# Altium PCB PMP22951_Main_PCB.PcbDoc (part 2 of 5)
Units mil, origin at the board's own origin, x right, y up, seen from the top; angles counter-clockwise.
Board outline 6643.5 x 4153.54 mil, 6 copper layers (Top Layer, Signal Layer 1, Signal Layer 2, Signal Layer 3, Signal Layer 4, Bottom Layer), stack 65.8 mil thick; 139 components, 80 nets, 687 pads, 417 vias.
Unrouted connection lines stored in the file: 2.
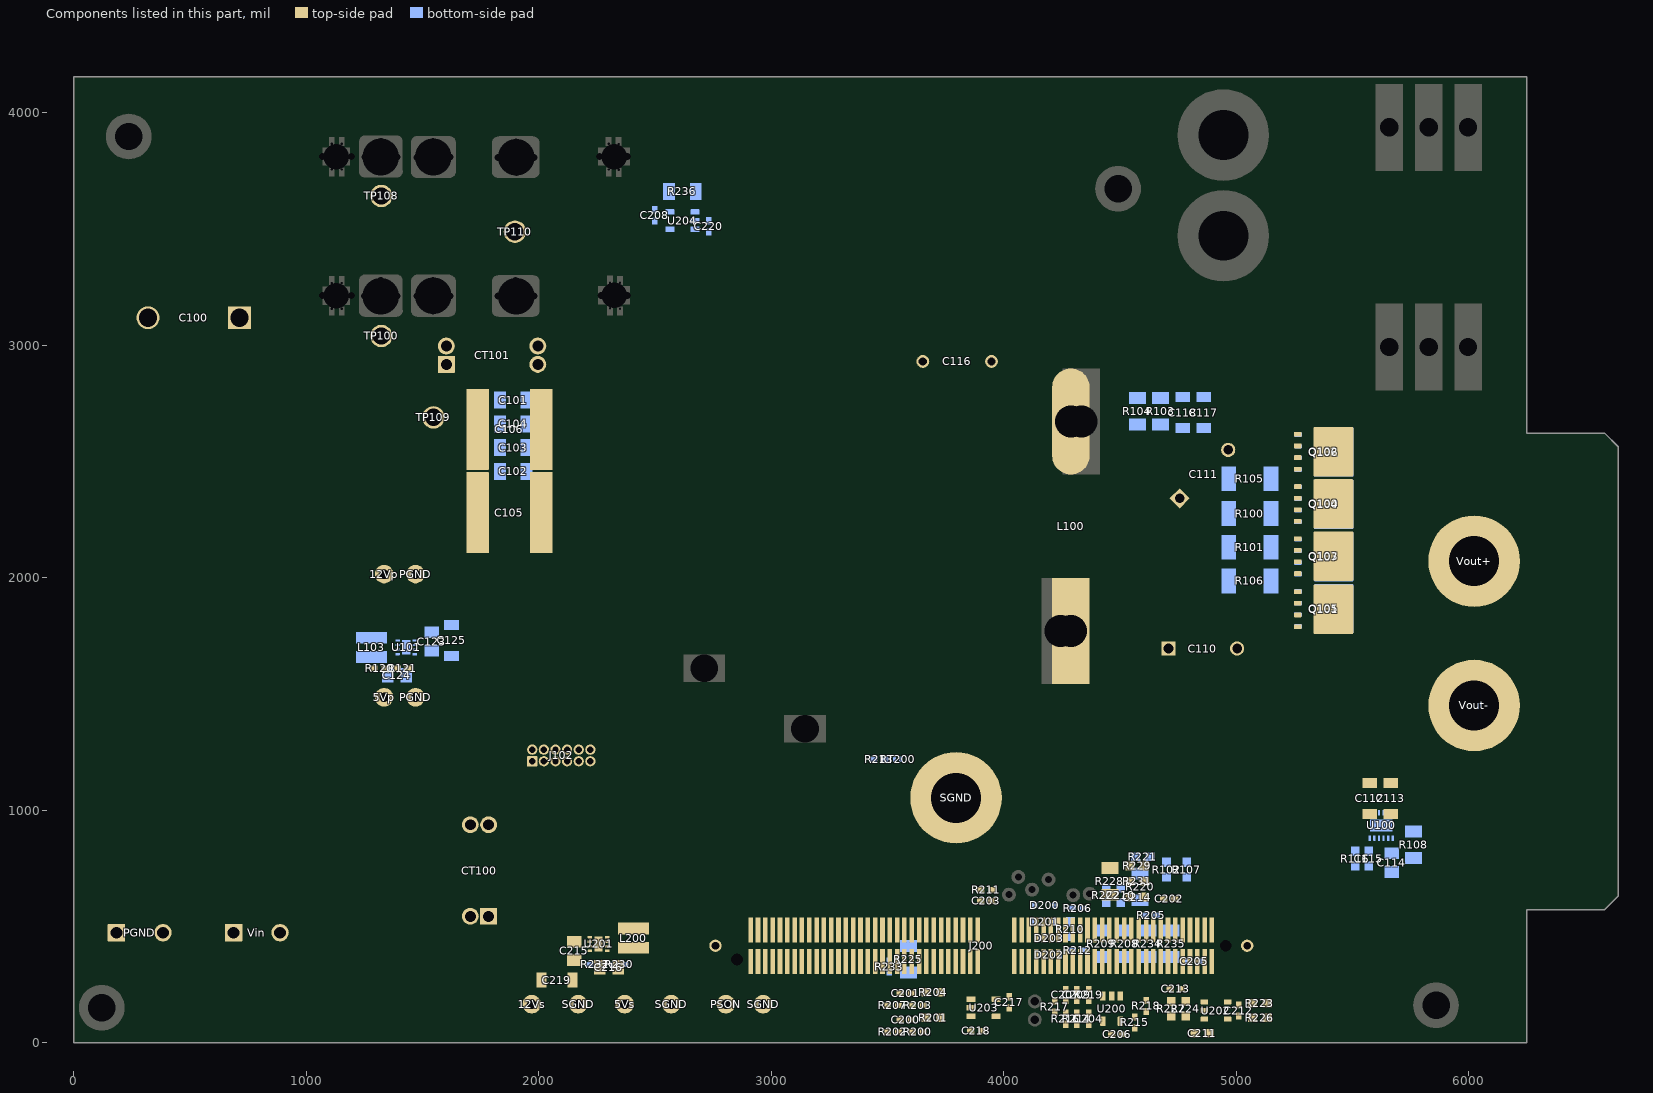
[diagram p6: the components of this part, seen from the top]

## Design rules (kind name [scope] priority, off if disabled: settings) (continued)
PolygonConnect PolygonConnect_49 [All vs IsNamedPolygon('BOTTOM_LAYER_54V1_P128')] p20: connectstyle=Direct reliefconductorwidth=10 reliefentries=4 polygonreliefangle="90 Angle" airgapwidth=10
PolygonConnect PolygonConnect_48 [All vs IsNamedPolygon('BOTTOM_LAYER_54V1_P128')] p21: connectstyle=Direct reliefconductorwidth=10 reliefentries=4 polygonreliefangle="90 Angle" airgapwidth=10
PolygonConnect PolygonConnect_47 [All vs IsNamedPolygon('BOTTOM_LAYER_54V1_P128')] p22: connectstyle=Direct reliefconductorwidth=10 reliefentries=4 polygonreliefangle="90 Angle" airgapwidth=10
PolygonConnect PolygonConnect_46 [All vs IsNamedPolygon('PGND') Or  IsNamedPolygon('T200_4') Or  IsNamedPolygon('VBB') Or  IsNamedPolygon('SWNODE3') Or  IsNamedPolygon('LEG4_LS_DRV') Or  IsNamedPolygon('Iout_SNS') Or  IsNamedPolygon('SWNODE3') Or  IsNamedPolygon('T200_6') Or  IsNamedPolygon('SGND') Or  IsNamedPolygon('SIGNAL_LAYER_1_VBULK1_P106') Or  IsNamedPolygon('LEG3_HS_DRV') Or  IsNamedPolygon('TOP_LAYER_12VS_P126') Or  IsNamedPolygon('LEG4_HS_DRV') Or  IsNamedPolygon('SWNODE3') Or  IsNamedPolygon('SGND') Or  IsNamedPolygon('BOTTOM_LAYER_54V1_P128') Or  IsNamedPolygon('SGND') Or  IsNamedPolygon('Line') Or  IsNamedPolygon('TOP_LAYER_IOUT_SNS_P092') Or  IsNamedPolygon('C108_1') Or  IsNamedPolygon('D403_2') Or  IsNamedPolygon('SWNODE') Or  IsNamedPolygon('SIGNAL_LAYER_2_VBB_P094') Or  IsNamedPolygon('Vbulk') Or  IsNamedPolygon('D404_2') Or  IsNamedPolygon('VSR') Or  IsNamedPolygon('C108_1') Or  IsNamedPolygon('C108_1') Or  IsNamedPolygon('5Vp') Or  IsNamedPolygon('C108_1') Or  IsNamedPolygon('PGND') Or  IsNamedPolygon('D400_2') Or  IsNamedPolygon('SWNODE3') Or  IsNamedPolygon('Line') Or  IsNamedPolygon('C108_1') Or  IsNamedPolygon('TOP_LAYER_VBULK_P104') Or  IsNamedPolygon('Vbulk1') Or  IsNamedPolygon('T200_6') Or  IsNamedPolygon('T200_6') Or  IsNamedPolygon('SWNODE4') Or  IsNamedPolygon('C108_1') Or  IsNamedPolygon('D403_2') Or  IsNamedPolygon('PGND') Or  IsNamedPolygon('T200_4') Or  IsNamedPolygon('Line') Or  IsNamedPolygon('5Vs') Or  IsNamedPolygon('12Vp') Or  IsNamedPolygon('C102_1') Or  IsNamedPolygon('SGND') Or  IsNamedPolygon('TOP_LAYER_54V2_P048') Or  IsNamedPolygon('TOP_LAYER_54V1_P046') Or  IsNamedPolygon('SWNODE4') Or  IsNamedPolygon('ZCD') Or  IsNamedPolygon('SWNODE3') Or  IsNamedPolygon('SWNODE3') Or  IsNamedPolygon('BOTTOM_LAYER_NETC106_2_P030') Or  IsNamedPolygon('TOP_LAYER_54V2_P048') Or  IsNamedPolygon('T200_4') Or  IsNamedPolygon('SWNODE4') Or  IsNamedPolygon('SWNODE4') Or  IsNamedPolygon('SGND') Or  IsNamedPolygon('SGND') Or  IsNamedPolygon('SGND') Or  IsNamedPolygon('SWNODE4') Or  IsNamedPolygon('VSR') Or  IsNamedPolygon('SWNODE3') Or  IsNamedPolygon('SGND') Or  IsNamedPolygon('SGND') Or  IsNamedPolygon('SGND') Or  IsNamedPolygon('SGND') Or  IsNamedPolygon('SGND') Or  IsNamedPolygon('SGND') Or  IsNamedPolygon('BOTTOM_LAYER_54V1_P128') Or  IsNamedPolygon('SGND') Or  IsNamedPolygon('VSR') Or  IsNamedPolygon('C102_1') Or  IsNamedPolygon('C102_1') Or  IsNamedPolygon('C102_1') Or  IsNamedPolygon('C102_1') Or  IsNamedPolygon('C102_1') Or  IsNamedPolygon('ZCD') Or  IsNamedPolygon('PGND') Or  IsNamedPolygon('PGND') Or  IsNamedPolygon('Vbulk1') Or  IsNamedPolygon('Vbulk') Or  IsNamedPolygon('Vbulk1') Or  IsNamedPolygon('Vbulk1') Or  IsNamedPolygon('ZCD') Or  IsNamedPolygon('Neutral') Or  IsNamedPolygon('Neutral') Or  IsNamedPolygon('C106_2') Or  IsNamedPolygon('C106_2') Or  IsNamedPolygon('C106_2') Or  IsNamedPolygon('SWNODE') Or  IsNamedPolygon('Vbulk1') Or  IsNamedPolygon('Earth1') Or  IsNamedPolygon('Earth1') Or  IsNamedPolygon('Earth1') Or  IsNamedPolygon('Earth1') Or  IsNamedPolygon('Earth1') Or  IsNamedPolygon('Earth1') Or  IsNamedPolygon('ZCD') Or  IsNamedPolygon('VBB') Or  IsNamedPolygon('PGND') Or  IsNamedPolygon('D106_1') Or  IsNamedPolygon('PGND') Or  IsNamedPolygon('PGND') Or  IsNamedPolygon('D106_1') Or  IsNamedPolygon('Vbulk') Or  IsNamedPolygon('D106_1') Or  IsNamedPolygon('PGND') Or  IsNamedPolygon('VBB') Or  IsNamedPolygon('VBB') Or  IsNamedPolygon('PGND') Or  IsNamedPolygon('PGND') Or  IsNamedPolygon('PGND') Or  IsNamedPolygon('PGND') Or  IsNamedPolygon('PGND') Or  IsNamedPolygon('ZCD') Or  IsNamedPolygon('ZCD') Or  IsNamedPolygon('C412_2') Or  IsNamedPolygon('VBB') Or  IsNamedPolygon('PGND') Or  IsNamedPolygon('PGND') Or  IsNamedPolygon('PGND') Or  IsNamedPolygon('PGND') Or  IsNamedPolygon('PGND') Or  IsNamedPolygon('PGND') Or  IsNamedPolygon('PGND') Or  IsNamedPolygon('Vbulk') Or  IsNamedPolygon('D404_2') Or  IsNamedPolygon('PGND') Or  IsNamedPolygon('Iout_SNS') Or  IsNamedPolygon('54V2')] p23: connectstyle=Direct reliefconductorwidth=10 reliefentries=4 polygonreliefangle="90 Angle" airgapwidth=10
PolygonConnect PolygonConnect_45 [All vs IsNamedPolygon('Vbulk1') Or  IsNamedPolygon('TOP_LAYER_VBULK_P104') Or  IsNamedPolygon('SIGNAL_LAYER_1_VBULK1_P106') Or  IsNamedPolygon('Iout_SNS') Or  IsNamedPolygon('SIGNAL_LAYER_2_VBB_P094') Or  IsNamedPolygon('Line') Or  IsNamedPolygon('T200_4') Or  IsNamedPolygon('ZCD') Or  IsNamedPolygon('C108_1') Or  IsNamedPolygon('PGND') Or  IsNamedPolygon('BOTTOM_LAYER_NETC106_2_P030') Or  IsNamedPolygon('5Vp') Or  IsNamedPolygon('C108_1') Or  IsNamedPolygon('Line') Or  IsNamedPolygon('C102_1') Or  IsNamedPolygon('T200_4') Or  IsNamedPolygon('12Vp') Or  IsNamedPolygon('D403_2') Or  IsNamedPolygon('T200_6') Or  IsNamedPolygon('TOP_LAYER_54V1_P046') Or  IsNamedPolygon('TOP_LAYER_54V2_P048') Or  IsNamedPolygon('C108_1') Or  IsNamedPolygon('C108_1') Or  IsNamedPolygon('SWNODE3') Or  IsNamedPolygon('TOP_LAYER_54V2_P048') Or  IsNamedPolygon('PGND') Or  IsNamedPolygon('D403_2') Or  IsNamedPolygon('C108_1') Or  IsNamedPolygon('C108_1') Or  IsNamedPolygon('T200_6') Or  IsNamedPolygon('SGND') Or  IsNamedPolygon('SWNODE') Or  IsNamedPolygon('SGND') Or  IsNamedPolygon('SWNODE3') Or  IsNamedPolygon('BOTTOM_LAYER_54V1_P128') Or  IsNamedPolygon('C102_1') Or  IsNamedPolygon('SWNODE4') Or  IsNamedPolygon('C102_1') Or  IsNamedPolygon('SGND') Or  IsNamedPolygon('C102_1') Or  IsNamedPolygon('SGND') Or  IsNamedPolygon('VSR') Or  IsNamedPolygon('SGND') Or  IsNamedPolygon('SGND') Or  IsNamedPolygon('VSR') Or  IsNamedPolygon('SGND') Or  IsNamedPolygon('SWNODE4') Or  IsNamedPolygon('SGND') Or  IsNamedPolygon('SGND') Or  IsNamedPolygon('Vbulk1') Or  IsNamedPolygon('SGND') Or  IsNamedPolygon('PGND') Or  IsNamedPolygon('SGND') Or  IsNamedPolygon('PGND') Or  IsNamedPolygon('SWNODE3') Or  IsNamedPolygon('ZCD') Or  IsNamedPolygon('VSR') Or  IsNamedPolygon('C102_1') Or  IsNamedPolygon('SWNODE4') Or  IsNamedPolygon('C102_1') Or  IsNamedPolygon('SWNODE4') Or  IsNamedPolygon('SWNODE3') Or  IsNamedPolygon('PGND') Or  IsNamedPolygon('SGND') Or  IsNamedPolygon('D400_2') Or  IsNamedPolygon('SGND') Or  IsNamedPolygon('5Vs') Or  IsNamedPolygon('VBB') Or  IsNamedPolygon('T200_4') Or  IsNamedPolygon('T200_6') Or  IsNamedPolygon('SWNODE4') Or  IsNamedPolygon('LEG4_HS_DRV') Or  IsNamedPolygon('LEG4_LS_DRV') Or  IsNamedPolygon('LEG3_HS_DRV') Or  IsNamedPolygon('BOTTOM_LAYER_54V1_P128') Or  IsNamedPolygon('TOP_LAYER_12VS_P126') Or  IsNamedPolygon('Iout_SNS') Or  IsNamedPolygon('SWNODE3') Or  IsNamedPolygon('SWNODE3') Or  IsNamedPolygon('SWNODE3') Or  IsNamedPolygon('VBB') Or  IsNamedPolygon('Line') Or  IsNamedPolygon('D404_2') Or  IsNamedPolygon('SGND') Or  IsNamedPolygon('VBB') Or  IsNamedPolygon('VBB') Or  IsNamedPolygon('PGND') Or  IsNamedPolygon('PGND') Or  IsNamedPolygon('PGND') Or  IsNamedPolygon('PGND') Or  IsNamedPolygon('PGND') Or  IsNamedPolygon('ZCD') Or  IsNamedPolygon('ZCD') Or  IsNamedPolygon('C412_2') Or  IsNamedPolygon('VBB') Or  IsNamedPolygon('PGND') Or  IsNamedPolygon('PGND') Or  IsNamedPolygon('PGND') Or  IsNamedPolygon('PGND') Or  IsNamedPolygon('PGND') Or  IsNamedPolygon('PGND') Or  IsNamedPolygon('PGND') Or  IsNamedPolygon('VBB') Or  IsNamedPolygon('D404_2') Or  IsNamedPolygon('VBB') Or  IsNamedPolygon('Vbulk1') Or  IsNamedPolygon('Vbulk1') Or  IsNamedPolygon('ZCD') Or  IsNamedPolygon('Neutral') Or  IsNamedPolygon('Neutral') Or  IsNamedPolygon('C106_2') Or  IsNamedPolygon('C106_2') Or  IsNamedPolygon('C106_2') Or  IsNamedPolygon('SWNODE') Or  IsNamedPolygon('Vbulk1') Or  IsNamedPolygon('Earth1') Or  IsNamedPolygon('Earth1') Or  IsNamedPolygon('Earth1') Or  IsNamedPolygon('Earth1') Or  IsNamedPolygon('Earth1') Or  IsNamedPolygon('Earth1') Or  IsNamedPolygon('ZCD') Or  IsNamedPolygon('VBB') Or  IsNamedPolygon('PGND') Or  IsNamedPolygon('D106_1') Or  IsNamedPolygon('PGND') Or  IsNamedPolygon('PGND') Or  IsNamedPolygon('D106_1') Or  IsNamedPolygon('VBB') Or  IsNamedPolygon('D106_1') Or  IsNamedPolygon('PGND')] p24: connectstyle=Direct reliefconductorwidth=10 reliefentries=4 polygonreliefangle="90 Angle" airgapwidth=10
PolygonConnect PolygonConnect_44 [All vs IsNamedPolygon('Earth1') Or  IsNamedPolygon('Vbulk1') Or  IsNamedPolygon('Vbulk1') Or  IsNamedPolygon('VBB') Or  IsNamedPolygon('Vbulk1') Or  IsNamedPolygon('ZCD') Or  IsNamedPolygon('VBB') Or  IsNamedPolygon('PGND') Or  IsNamedPolygon('C412_2') Or  IsNamedPolygon('ZCD') Or  IsNamedPolygon('D106_1') Or  IsNamedPolygon('D106_1') Or  IsNamedPolygon('ZCD') Or  IsNamedPolygon('PGND') Or  IsNamedPolygon('PGND') Or  IsNamedPolygon('ZCD') Or  IsNamedPolygon('VBB') Or  IsNamedPolygon('PGND') Or  IsNamedPolygon('VBB') Or  IsNamedPolygon('PGND') Or  IsNamedPolygon('D106_1') Or  IsNamedPolygon('PGND') Or  IsNamedPolygon('PGND') Or  IsNamedPolygon('PGND') Or  IsNamedPolygon('VBB') Or  IsNamedPolygon('PGND') Or  IsNamedPolygon('PGND') Or  IsNamedPolygon('C102_1') Or  IsNamedPolygon('ZCD') Or  IsNamedPolygon('C102_1') Or  IsNamedPolygon('C102_1') Or  IsNamedPolygon('C102_1') Or  IsNamedPolygon('PGND') Or  IsNamedPolygon('C102_1') Or  IsNamedPolygon('Line') Or  IsNamedPolygon('T200_4') Or  IsNamedPolygon('T200_4') Or  IsNamedPolygon('SIGNAL_LAYER_1_VBULK1_P106') Or  IsNamedPolygon('TOP_LAYER_VBULK_P104') Or  IsNamedPolygon('T200_4') Or  IsNamedPolygon('SGND') Or  IsNamedPolygon('T200_6') Or  IsNamedPolygon('C108_1') Or  IsNamedPolygon('SWNODE3') Or  IsNamedPolygon('SWNODE') Or  IsNamedPolygon('SWNODE3') Or  IsNamedPolygon('LEG3_HS_DRV') Or  IsNamedPolygon('BOTTOM_LAYER_NETC106_2_P030') Or  IsNamedPolygon('C102_1') Or  IsNamedPolygon('SWNODE4') Or  IsNamedPolygon('SIGNAL_LAYER_2_VBB_P094') Or  IsNamedPolygon('SGND') Or  IsNamedPolygon('VSR') Or  IsNamedPolygon('C108_1') Or  IsNamedPolygon('BOTTOM_LAYER_54V1_P128') Or  IsNamedPolygon('TOP_LAYER_54V2_P048') Or  IsNamedPolygon('TOP_LAYER_54V1_P046') Or  IsNamedPolygon('C108_1') Or  IsNamedPolygon('D403_2') Or  IsNamedPolygon('ZCD') Or  IsNamedPolygon('PGND') Or  IsNamedPolygon('SWNODE3') Or  IsNamedPolygon('Line') Or  IsNamedPolygon('D400_2') Or  IsNamedPolygon('SGND') Or  IsNamedPolygon('PGND') Or  IsNamedPolygon('SGND') Or  IsNamedPolygon('LEG4_HS_DRV') Or  IsNamedPolygon('SWNODE3') Or  IsNamedPolygon('5Vs') Or  IsNamedPolygon('SWNODE4') Or  IsNamedPolygon('SGND') Or  IsNamedPolygon('SGND') Or  IsNamedPolygon('C108_1') Or  IsNamedPolygon('5Vp') Or  IsNamedPolygon('12Vp') Or  IsNamedPolygon('Iout_SNS') Or  IsNamedPolygon('D404_2') Or  IsNamedPolygon('SGND') Or  IsNamedPolygon('T200_6') Or  IsNamedPolygon('TOP_LAYER_54V2_P048') Or  IsNamedPolygon('SGND') Or  IsNamedPolygon('SWNODE3') Or  IsNamedPolygon('SWNODE4') Or  IsNamedPolygon('Iout_SNS') Or  IsNamedPolygon('C108_1') Or  IsNamedPolygon('BOTTOM_LAYER_54V1_P128') Or  IsNamedPolygon('SWNODE3') Or  IsNamedPolygon('LEG4_LS_DRV') Or  IsNamedPolygon('SGND') Or  IsNamedPolygon('SWNODE4') Or  IsNamedPolygon('T200_6') Or  IsNamedPolygon('TOP_LAYER_12VS_P126') Or  IsNamedPolygon('Line') Or  IsNamedPolygon('Vbulk1') Or  IsNamedPolygon('SWNODE3') Or  IsNamedPolygon('SGND') Or  IsNamedPolygon('VBB') Or  IsNamedPolygon('SGND') Or  IsNamedPolygon('SGND') Or  IsNamedPolygon('SWNODE4') Or  IsNamedPolygon('PGND') Or  IsNamedPolygon('D403_2') Or  IsNamedPolygon('VSR') Or  IsNamedPolygon('SGND') Or  IsNamedPolygon('SGND') Or  IsNamedPolygon('VBB') Or  IsNamedPolygon('C108_1') Or  IsNamedPolygon('Earth1') Or  IsNamedPolygon('Earth1') Or  IsNamedPolygon('VSR') Or  IsNamedPolygon('C106_2') Or  IsNamedPolygon('Vbulk1') Or  IsNamedPolygon('C106_2') Or  IsNamedPolygon('C106_2') Or  IsNamedPolygon('Earth1') Or  IsNamedPolygon('SWNODE') Or  IsNamedPolygon('Neutral') Or  IsNamedPolygon('Earth1') Or  IsNamedPolygon('Earth1') Or  IsNamedPolygon('Neutral')] p25: connectstyle=Direct reliefconductorwidth=10 reliefentries=4 polygonreliefangle="90 Angle" airgapwidth=10
PolygonConnect PolygonConnect_43 [All vs IsNamedPolygon('SWNODE') Or  IsNamedPolygon('D403_2') Or  IsNamedPolygon('D403_2') Or  IsNamedPolygon('PGND') Or  IsNamedPolygon('BOTTOM_LAYER_NETC106_2_P030') Or  IsNamedPolygon('C102_1') Or  IsNamedPolygon('SGND') Or  IsNamedPolygon('TOP_LAYER_54V1_P046') Or  IsNamedPolygon('TOP_LAYER_54V2_P048') Or  IsNamedPolygon('TOP_LAYER_54V2_P048') Or  IsNamedPolygon('C108_1') Or  IsNamedPolygon('C108_1') Or  IsNamedPolygon('C108_1') Or  IsNamedPolygon('C108_1') Or  IsNamedPolygon('C108_1') Or  IsNamedPolygon('C108_1') Or  IsNamedPolygon('PGND') Or  IsNamedPolygon('ZCD') Or  IsNamedPolygon('Line') Or  IsNamedPolygon('5Vp') Or  IsNamedPolygon('12Vp') Or  IsNamedPolygon('T200_4') Or  IsNamedPolygon('T200_6') Or  IsNamedPolygon('SWNODE3') Or  IsNamedPolygon('T200_4') Or  IsNamedPolygon('T200_6') Or  IsNamedPolygon('SWNODE4') Or  IsNamedPolygon('VSR') Or  IsNamedPolygon('Iout_SNS') Or  IsNamedPolygon('SIGNAL_LAYER_2_VBB_P094') Or  IsNamedPolygon('Vbulk1') Or  IsNamedPolygon('TOP_LAYER_VBULK_P104') Or  IsNamedPolygon('SIGNAL_LAYER_1_VBULK1_P106') Or  IsNamedPolygon('Line') Or  IsNamedPolygon('Line') Or  IsNamedPolygon('D404_2') Or  IsNamedPolygon('VBB') Or  IsNamedPolygon('D400_2') Or  IsNamedPolygon('SGND') Or  IsNamedPolygon('PGND') Or  IsNamedPolygon('TOP_LAYER_12VS_P126') Or  IsNamedPolygon('BOTTOM_LAYER_54V1_P128') Or  IsNamedPolygon('LEG3_HS_DRV') Or  IsNamedPolygon('LEG4_LS_DRV') Or  IsNamedPolygon('LEG4_HS_DRV') Or  IsNamedPolygon('SWNODE4') Or  IsNamedPolygon('SWNODE3') Or  IsNamedPolygon('T200_6') Or  IsNamedPolygon('T200_4') Or  IsNamedPolygon('VBB') Or  IsNamedPolygon('5Vs') Or  IsNamedPolygon('SGND') Or  IsNamedPolygon('Iout_SNS') Or  IsNamedPolygon('SGND') Or  IsNamedPolygon('SWNODE3') Or  IsNamedPolygon('SWNODE3') Or  IsNamedPolygon('SWNODE3') Or  IsNamedPolygon('SWNODE3') Or  IsNamedPolygon('SGND') Or  IsNamedPolygon('SGND') Or  IsNamedPolygon('SGND') Or  IsNamedPolygon('SWNODE4') Or  IsNamedPolygon('SWNODE4') Or  IsNamedPolygon('SWNODE4') Or  IsNamedPolygon('VSR') Or  IsNamedPolygon('SWNODE3') Or  IsNamedPolygon('SGND') Or  IsNamedPolygon('SGND') Or  IsNamedPolygon('SGND') Or  IsNamedPolygon('SGND') Or  IsNamedPolygon('SGND') Or  IsNamedPolygon('SGND') Or  IsNamedPolygon('BOTTOM_LAYER_54V1_P128') Or  IsNamedPolygon('SGND') Or  IsNamedPolygon('VSR') Or  IsNamedPolygon('C102_1') Or  IsNamedPolygon('C102_1') Or  IsNamedPolygon('C102_1') Or  IsNamedPolygon('C102_1') Or  IsNamedPolygon('C102_1') Or  IsNamedPolygon('ZCD') Or  IsNamedPolygon('PGND') Or  IsNamedPolygon('PGND') Or  IsNamedPolygon('Vbulk1') Or  IsNamedPolygon('VBB') Or  IsNamedPolygon('Vbulk1') Or  IsNamedPolygon('Vbulk1') Or  IsNamedPolygon('ZCD') Or  IsNamedPolygon('Neutral') Or  IsNamedPolygon('Neutral') Or  IsNamedPolygon('C106_2') Or  IsNamedPolygon('C106_2') Or  IsNamedPolygon('C106_2') Or  IsNamedPolygon('SWNODE') Or  IsNamedPolygon('Vbulk1') Or  IsNamedPolygon('Earth1') Or  IsNamedPolygon('Earth1') Or  IsNamedPolygon('Earth1') Or  IsNamedPolygon('Earth1') Or  IsNamedPolygon('Earth1') Or  IsNamedPolygon('Earth1') Or  IsNamedPolygon('ZCD') Or  IsNamedPolygon('VBB') Or  IsNamedPolygon('PGND') Or  IsNamedPolygon('D106_1') Or  IsNamedPolygon('PGND') Or  IsNamedPolygon('PGND') Or  IsNamedPolygon('D106_1') Or  IsNamedPolygon('VBB') Or  IsNamedPolygon('D106_1') Or  IsNamedPolygon('PGND') Or  IsNamedPolygon('VBB') Or  IsNamedPolygon('VBB') Or  IsNamedPolygon('PGND') Or  IsNamedPolygon('PGND') Or  IsNamedPolygon('PGND') Or  IsNamedPolygon('PGND') Or  IsNamedPolygon('PGND')] p26: connectstyle=Direct reliefconductorwidth=10 reliefentries=4 polygonreliefangle="90 Angle" airgapwidth=10
PolygonConnect PolygonConnect_42 [All vs IsNamedPolygon('Neutral') Or  IsNamedPolygon('Earth1') Or  IsNamedPolygon('Earth1') Or  IsNamedPolygon('D404_2') Or  IsNamedPolygon('Line') Or  IsNamedPolygon('SIGNAL_LAYER_1_VBULK1_P106') Or  IsNamedPolygon('Line') Or  IsNamedPolygon('C102_1') Or  IsNamedPolygon('SWNODE3') Or  IsNamedPolygon('SWNODE3') Or  IsNamedPolygon('SWNODE') Or  IsNamedPolygon('5Vp') Or  IsNamedPolygon('T200_6') Or  IsNamedPolygon('SWNODE3') Or  IsNamedPolygon('SGND') Or  IsNamedPolygon('SWNODE3') Or  IsNamedPolygon('VSR') Or  IsNamedPolygon('C108_1') Or  IsNamedPolygon('SWNODE3') Or  IsNamedPolygon('TOP_LAYER_12VS_P126') Or  IsNamedPolygon('SGND') Or  IsNamedPolygon('SGND') Or  IsNamedPolygon('SGND') Or  IsNamedPolygon('T200_6') Or  IsNamedPolygon('SWNODE4') Or  IsNamedPolygon('C108_1') Or  IsNamedPolygon('C106_2') Or  IsNamedPolygon('SGND') Or  IsNamedPolygon('Neutral') Or  IsNamedPolygon('SIGNAL_LAYER_2_VBB_P094') Or  IsNamedPolygon('Vbulk1') Or  IsNamedPolygon('SGND') Or  IsNamedPolygon('SGND') Or  IsNamedPolygon('TOP_LAYER_54V1_P046') Or  IsNamedPolygon('TOP_LAYER_54V2_P048') Or  IsNamedPolygon('TOP_LAYER_54V2_P048') Or  IsNamedPolygon('C102_1') Or  IsNamedPolygon('SGND') Or  IsNamedPolygon('T200_4') Or  IsNamedPolygon('12Vp') Or  IsNamedPolygon('SGND') Or  IsNamedPolygon('D400_2') Or  IsNamedPolygon('LEG3_HS_DRV') Or  IsNamedPolygon('LEG4_LS_DRV') Or  IsNamedPolygon('T200_4') Or  IsNamedPolygon('BOTTOM_LAYER_54V1_P128') Or  IsNamedPolygon('SGND') Or  IsNamedPolygon('VBB') Or  IsNamedPolygon('SWNODE4') Or  IsNamedPolygon('SWNODE4') Or  IsNamedPolygon('SWNODE4') Or  IsNamedPolygon('VSR') Or  IsNamedPolygon('Iout_SNS') Or  IsNamedPolygon('VBB') Or  IsNamedPolygon('PGND') Or  IsNamedPolygon('Line') Or  IsNamedPolygon('ZCD') Or  IsNamedPolygon('D403_2') Or  IsNamedPolygon('SWNODE3') Or  IsNamedPolygon('Vbulk1') Or  IsNamedPolygon('ZCD') Or  IsNamedPolygon('LEG4_HS_DRV') Or  IsNamedPolygon('BOTTOM_LAYER_54V1_P128') Or  IsNamedPolygon('VBB') Or  IsNamedPolygon('PGND') Or  IsNamedPolygon('ZCD') Or  IsNamedPolygon('ZCD') Or  IsNamedPolygon('Earth1') Or  IsNamedPolygon('VBB') Or  IsNamedPolygon('PGND') Or  IsNamedPolygon('PGND') Or  IsNamedPolygon('Vbulk1') Or  IsNamedPolygon('SWNODE') Or  IsNamedPolygon('C106_2') Or  IsNamedPolygon('C106_2') Or  IsNamedPolygon('C108_1') Or  IsNamedPolygon('SWNODE3') Or  IsNamedPolygon('SWNODE4') Or  IsNamedPolygon('Vbulk1') Or  IsNamedPolygon('SGND') Or  IsNamedPolygon('C102_1') Or  IsNamedPolygon('BOTTOM_LAYER_NETC106_2_P030') Or  IsNamedPolygon('Earth1') Or  IsNamedPolygon('Earth1') Or  IsNamedPolygon('Vbulk1') Or  IsNamedPolygon('Earth1') Or  IsNamedPolygon('T200_6') Or  IsNamedPolygon('T200_4') Or  IsNamedPolygon('C102_1') Or  IsNamedPolygon('C102_1') Or  IsNamedPolygon('C102_1') Or  IsNamedPolygon('VBB') Or  IsNamedPolygon('5Vs') Or  IsNamedPolygon('SGND') Or  IsNamedPolygon('Iout_SNS') Or  IsNamedPolygon('C108_1') Or  IsNamedPolygon('C108_1') Or  IsNamedPolygon('C108_1') Or  IsNamedPolygon('PGND') Or  IsNamedPolygon('D403_2') Or  IsNamedPolygon('PGND') Or  IsNamedPolygon('SGND') Or  IsNamedPolygon('SGND') Or  IsNamedPolygon('VSR')] p27: connectstyle=Direct reliefconductorwidth=10 reliefentries=4 polygonreliefangle="90 Angle" airgapwidth=10
PolygonConnect PolygonConnect_41 [All vs IsNamedPolygon('VBB') Or  IsNamedPolygon('SWNODE3') Or  IsNamedPolygon('T200_4') Or  IsNamedPolygon('Earth1') Or  IsNamedPolygon('BOTTOM_LAYER_54V1_P128') Or  IsNamedPolygon('SGND') Or  IsNamedPolygon('TOP_LAYER_12VS_P126') Or  IsNamedPolygon('C102_1') Or  IsNamedPolygon('VSR') Or  IsNamedPolygon('Earth1') Or  IsNamedPolygon('Neutral') Or  IsNamedPolygon('Vbulk1') Or  IsNamedPolygon('SWNODE4') Or  IsNamedPolygon('C106_2') Or  IsNamedPolygon('PGND') Or  IsNamedPolygon('SGND') Or  IsNamedPolygon('VBB') Or  IsNamedPolygon('PGND') Or  IsNamedPolygon('LEG4_LS_DRV') Or  IsNamedPolygon('C102_1') Or  IsNamedPolygon('SWNODE4') Or  IsNamedPolygon('C106_2') Or  IsNamedPolygon('Vbulk1') Or  IsNamedPolygon('C102_1') Or  IsNamedPolygon('BOTTOM_LAYER_54V1_P128') Or  IsNamedPolygon('LEG3_HS_DRV') Or  IsNamedPolygon('SGND') Or  IsNamedPolygon('SGND') Or  IsNamedPolygon('Earth1') Or  IsNamedPolygon('SGND') Or  IsNamedPolygon('SGND') Or  IsNamedPolygon('5Vs') Or  IsNamedPolygon('LEG4_HS_DRV') Or  IsNamedPolygon('Earth1') Or  IsNamedPolygon('SGND') Or  IsNamedPolygon('SWNODE3') Or  IsNamedPolygon('Iout_SNS') Or  IsNamedPolygon('ZCD') Or  IsNamedPolygon('Earth1') Or  IsNamedPolygon('VSR') Or  IsNamedPolygon('C102_1') Or  IsNamedPolygon('C102_1') Or  IsNamedPolygon('Vbulk1') Or  IsNamedPolygon('C106_2') Or  IsNamedPolygon('ZCD') Or  IsNamedPolygon('SWNODE3') Or  IsNamedPolygon('SWNODE3') Or  IsNamedPolygon('Vbulk1') Or  IsNamedPolygon('SWNODE4') Or  IsNamedPolygon('Neutral') Or  IsNamedPolygon('SWNODE3') Or  IsNamedPolygon('SWNODE4') Or  IsNamedPolygon('Earth1') Or  IsNamedPolygon('D400_2') Or  IsNamedPolygon('SGND') Or  IsNamedPolygon('SGND') Or  IsNamedPolygon('SGND') Or  IsNamedPolygon('SWNODE') Or  IsNamedPolygon('VSR') Or  IsNamedPolygon('SGND') Or  IsNamedPolygon('SIGNAL_LAYER_1_VBULK1_P106') Or  IsNamedPolygon('SGND') Or  IsNamedPolygon('T200_6') Or  IsNamedPolygon('SWNODE4') Or  IsNamedPolygon('VBB') Or  IsNamedPolygon('T200_6') Or  IsNamedPolygon('Line') Or  IsNamedPolygon('Iout_SNS') Or  IsNamedPolygon('Vbulk1') Or  IsNamedPolygon('VBB') Or  IsNamedPolygon('SIGNAL_LAYER_2_VBB_P094') Or  IsNamedPolygon('SGND') Or  IsNamedPolygon('D404_2') Or  IsNamedPolygon('SWNODE3') Or  IsNamedPolygon('Line') Or  IsNamedPolygon('PGND') Or  IsNamedPolygon('TOP_LAYER_54V2_P048') Or  IsNamedPolygon('TOP_LAYER_54V1_P046') Or  IsNamedPolygon('TOP_LAYER_54V2_P048') Or  IsNamedPolygon('C108_1') Or  IsNamedPolygon('BOTTOM_LAYER_NETC106_2_P030') Or  IsNamedPolygon('D403_2') Or  IsNamedPolygon('T200_4') Or  IsNamedPolygon('Line') Or  IsNamedPolygon('PGND') Or  IsNamedPolygon('SWNODE3') Or  IsNamedPolygon('ZCD') Or  IsNamedPolygon('SWNODE') Or  IsNamedPolygon('D403_2') Or  IsNamedPolygon('C108_1') Or  IsNamedPolygon('C102_1') Or  IsNamedPolygon('C108_1') Or  IsNamedPolygon('PGND') Or  IsNamedPolygon('C108_1') Or  IsNamedPolygon('C108_1') Or  IsNamedPolygon('5Vp') Or  IsNamedPolygon('T200_4') Or  IsNamedPolygon('12Vp') Or  IsNamedPolygon('T200_6') Or  IsNamedPolygon('C108_1') Or  IsNamedPolygon('SGND')] p28: connectstyle=Direct reliefconductorwidth=10 reliefentries=4 polygonreliefangle="90 Angle" airgapwidth=10
PolygonConnect PolygonConnect_40 [All vs IsNamedPolygon('Neutral')] p29: connectstyle=Direct reliefconductorwidth=10 reliefentries=4 polygonreliefangle="90 Angle" airgapwidth=10
PolygonConnect PolygonConnect_39 [All vs IsNamedPolygon('12Vp')] p30: connectstyle=Direct reliefconductorwidth=10 reliefentries=4 polygonreliefangle="90 Angle" airgapwidth=10
PolygonConnect PolygonConnect_38 [All vs IsNamedPolygon('SWNODE') Or  IsNamedPolygon('D403_2') Or  IsNamedPolygon('D403_2') Or  IsNamedPolygon('PGND') Or  IsNamedPolygon('BOTTOM_LAYER_NETC106_2_P030') Or  IsNamedPolygon('C102_1') Or  IsNamedPolygon('SGND') Or  IsNamedPolygon('TOP_LAYER_54V1_P046') Or  IsNamedPolygon('TOP_LAYER_54V2_P048') Or  IsNamedPolygon('TOP_LAYER_54V2_P048') Or  IsNamedPolygon('C108_1') Or  IsNamedPolygon('C108_1') Or  IsNamedPolygon('C108_1') Or  IsNamedPolygon('C108_1') Or  IsNamedPolygon('C108_1') Or  IsNamedPolygon('C108_1') Or  IsNamedPolygon('PGND') Or  IsNamedPolygon('ZCD') Or  IsNamedPolygon('Line') Or  IsNamedPolygon('5Vp') Or  IsNamedPolygon('12Vp') Or  IsNamedPolygon('T200_4') Or  IsNamedPolygon('T200_6') Or  IsNamedPolygon('SWNODE3') Or  IsNamedPolygon('T200_4') Or  IsNamedPolygon('T200_6') Or  IsNamedPolygon('SWNODE4') Or  IsNamedPolygon('VSR') Or  IsNamedPolygon('Iout_SNS') Or  IsNamedPolygon('SIGNAL_LAYER_2_VBB_P094') Or  IsNamedPolygon('Vbulk1') Or  IsNamedPolygon('VBB') Or  IsNamedPolygon('SIGNAL_LAYER_1_VBULK1_P106') Or  IsNamedPolygon('Line') Or  IsNamedPolygon('Line') Or  IsNamedPolygon('Line') Or  IsNamedPolygon('D404_2') Or  IsNamedPolygon('VBB') Or  IsNamedPolygon('D400_2') Or  IsNamedPolygon('SGND') Or  IsNamedPolygon('PGND') Or  IsNamedPolygon('TOP_LAYER_12VS_P126') Or  IsNamedPolygon('BOTTOM_LAYER_54V1_P128') Or  IsNamedPolygon('LEG3_HS_DRV') Or  IsNamedPolygon('LEG4_LS_DRV') Or  IsNamedPolygon('LEG4_HS_DRV') Or  IsNamedPolygon('SWNODE4') Or  IsNamedPolygon('SWNODE3') Or  IsNamedPolygon('T200_6') Or  IsNamedPolygon('T200_4') Or  IsNamedPolygon('VBB') Or  IsNamedPolygon('5Vs') Or  IsNamedPolygon('SGND') Or  IsNamedPolygon('Iout_SNS') Or  IsNamedPolygon('SGND') Or  IsNamedPolygon('SWNODE3') Or  IsNamedPolygon('SWNODE3') Or  IsNamedPolygon('SWNODE3') Or  IsNamedPolygon('SWNODE3') Or  IsNamedPolygon('SGND') Or  IsNamedPolygon('SGND') Or  IsNamedPolygon('SGND') Or  IsNamedPolygon('SWNODE4') Or  IsNamedPolygon('SWNODE4') Or  IsNamedPolygon('SWNODE4') Or  IsNamedPolygon('VSR') Or  IsNamedPolygon('SWNODE3') Or  IsNamedPolygon('SGND') Or  IsNamedPolygon('SGND') Or  IsNamedPolygon('SGND') Or  IsNamedPolygon('SGND') Or  IsNamedPolygon('SGND') Or  IsNamedPolygon('SGND') Or  IsNamedPolygon('BOTTOM_LAYER_54V1_P128') Or  IsNamedPolygon('SGND') Or  IsNamedPolygon('VSR') Or  IsNamedPolygon('C102_1') Or  IsNamedPolygon('C102_1') Or  IsNamedPolygon('C102_1') Or  IsNamedPolygon('C102_1') Or  IsNamedPolygon('C102_1') Or  IsNamedPolygon('ZCD') Or  IsNamedPolygon('PGND') Or  IsNamedPolygon('PGND') Or  IsNamedPolygon('Vbulk1') Or  IsNamedPolygon('VBB') Or  IsNamedPolygon('Vbulk1') Or  IsNamedPolygon('Vbulk1') Or  IsNamedPolygon('ZCD') Or  IsNamedPolygon('Neutral') Or  IsNamedPolygon('Neutral')] p31: connectstyle=Direct reliefconductorwidth=10 reliefentries=4 polygonreliefangle="90 Angle" airgapwidth=10
PolygonConnect PolygonConnect_37 [All vs IsNamedPolygon('SGND') Or  IsNamedPolygon('SWNODE4') Or  IsNamedPolygon('5Vp') Or  IsNamedPolygon('SWNODE4') Or  IsNamedPolygon('VBB') Or  IsNamedPolygon('Line') Or  IsNamedPolygon('SGND') Or  IsNamedPolygon('SIGNAL_LAYER_2_C102_1_P032') Or  IsNamedPolygon('TOP_LAYER_54V2_P048') Or  IsNamedPolygon('ZCD') Or  IsNamedPolygon('PGND') Or  IsNamedPolygon('SIGNAL_LAYER_2_VBB_P094') Or  IsNamedPolygon('Line') Or  IsNamedPolygon('Line') Or  IsNamedPolygon('D404_2') Or  IsNamedPolygon('PGND') Or  IsNamedPolygon('SIGNAL_LAYER_1_ZCD_P108') Or  IsNamedPolygon('SWNODE3') Or  IsNamedPolygon('SIGNAL_LAYER_4_C102_1_P038') Or  IsNamedPolygon('SWNODE3') Or  IsNamedPolygon('LEG4_HS_DRV') Or  IsNamedPolygon('SWNODE4') Or  IsNamedPolygon('5Vs') Or  IsNamedPolygon('VBB') Or  IsNamedPolygon('TOP_LAYER_54V2_P048') Or  IsNamedPolygon('C102_1') Or  IsNamedPolygon('LEG4_LS_DRV') Or  IsNamedPolygon('T200_4') Or  IsNamedPolygon('SWNODE3') Or  IsNamedPolygon('Line') Or  IsNamedPolygon('SGND') Or  IsNamedPolygon('SGND') Or  IsNamedPolygon('SWNODE4') Or  IsNamedPolygon('12Vp') Or  IsNamedPolygon('BOTTOM_LAYER_NETC106_2_P030') Or  IsNamedPolygon('T200_4') Or  IsNamedPolygon('Vbulk1') Or  IsNamedPolygon('C108_1') Or  IsNamedPolygon('BOTTOM_LAYER_54V1_P128') Or  IsNamedPolygon('BOTTOM_LAYER_54V1_P128') Or  IsNamedPolygon('SWNODE') Or  IsNamedPolygon('Iout_SNS') Or  IsNamedPolygon('VSR') Or  IsNamedPolygon('D400_2') Or  IsNamedPolygon('D403_2') Or  IsNamedPolygon('SWNODE3') Or  IsNamedPolygon('T200_6') Or  IsNamedPolygon('SWNODE3') Or  IsNamedPolygon('C108_1') Or  IsNamedPolygon('PGND') Or  IsNamedPolygon('BOTTOM_LAYER_VBULK1_P096') Or  IsNamedPolygon('BOTTOM_LAYER_54V1_P128') Or  IsNamedPolygon('TOP_LAYER_12VS_P126') Or  IsNamedPolygon('SIGNAL_LAYER_1_VBULK1_P106') Or  IsNamedPolygon('T200_4') Or  IsNamedPolygon('SGND') Or  IsNamedPolygon('C108_1') Or  IsNamedPolygon('SWNODE3') Or  IsNamedPolygon('T200_6') Or  IsNamedPolygon('T200_6') Or  IsNamedPolygon('T200_6') Or  IsNamedPolygon('SGND') Or  IsNamedPolygon('C108_1') Or  IsNamedPolygon('SGND') Or  IsNamedPolygon('VBB') Or  IsNamedPolygon('T200_4') Or  IsNamedPolygon('LEG3_HS_DRV') Or  IsNamedPolygon('C108_1') Or  IsNamedPolygon('D403_2') Or  IsNamedPolygon('Iout_SNS') Or  IsNamedPolygon('C108_1') Or  IsNamedPolygon('SWNODE4')] p32: connectstyle=Direct reliefconductorwidth=10 reliefentries=4 polygonreliefangle="90 Angle" airgapwidth=10
PolygonConnect PolygonConnect_36 [All vs IsNamedPolygon('PGND') Or  IsNamedPolygon('BOTTOM_LAYER_54V1_P128') Or  IsNamedPolygon('SGND') Or  IsNamedPolygon('LEG4_LS_DRV') Or  IsNamedPolygon('TOP_LAYER_12VS_P126') Or  IsNamedPolygon('LEG4_HS_DRV') Or  IsNamedPolygon('LEG3_HS_DRV') Or  IsNamedPolygon('SGND') Or  IsNamedPolygon('C108_1') Or  IsNamedPolygon('12Vp') Or  IsNamedPolygon('D403_2') Or  IsNamedPolygon('SIGNAL_LAYER_1_ZCD_P108') Or  IsNamedPolygon('C108_1') Or  IsNamedPolygon('BOTTOM_LAYER_VBULK1_P096') Or  IsNamedPolygon('SWNODE') Or  IsNamedPolygon('T200_4') Or  IsNamedPolygon('D400_2') Or  IsNamedPolygon('C102_1') Or  IsNamedPolygon('Line') Or  IsNamedPolygon('VBB') Or  IsNamedPolygon('Line') Or  IsNamedPolygon('TOP_LAYER_54V2_P048') Or  IsNamedPolygon('BOTTOM_LAYER_NETC106_2_P030') Or  IsNamedPolygon('SIGNAL_LAYER_1_VBULK1_P106') Or  IsNamedPolygon('Line') Or  IsNamedPolygon('5Vp') Or  IsNamedPolygon('BOTTOM_LAYER_54V1_P128') Or  IsNamedPolygon('D404_2') Or  IsNamedPolygon('C108_1') Or  IsNamedPolygon('VSR') Or  IsNamedPolygon('T200_6') Or  IsNamedPolygon('VBB') Or  IsNamedPolygon('C108_1') Or  IsNamedPolygon('SIGNAL_LAYER_2_C102_1_P032') Or  IsNamedPolygon('SGND') Or  IsNamedPolygon('PGND') Or  IsNamedPolygon('SIGNAL_LAYER_4_C102_1_P038') Or  IsNamedPolygon('Vbulk1') Or  IsNamedPolygon('TOP_LAYER_54V2_P048') Or  IsNamedPolygon('Iout_SNS') Or  IsNamedPolygon('PGND') Or  IsNamedPolygon('T200_4') Or  IsNamedPolygon('ZCD') Or  IsNamedPolygon('Line') Or  IsNamedPolygon('C108_1') Or  IsNamedPolygon('D403_2') Or  IsNamedPolygon('SIGNAL_LAYER_2_VBB_P094') Or  IsNamedPolygon('SGND') Or  IsNamedPolygon('C108_1') Or  IsNamedPolygon('SIGNAL_LAYER_1_IOUT_SNS_P044') Or  IsNamedPolygon('BOTTOM_LAYER_54V1_P128') Or  IsNamedPolygon('T200_6')] p33: connectstyle=Direct reliefconductorwidth=10 reliefentries=4 polygonreliefangle="90 Angle" airgapwidth=10
PolygonConnect PolygonConnect_35 [All vs IsNamedPolygon('SWNODE') Or  IsNamedPolygon('D403_2') Or  IsNamedPolygon('D403_2') Or  IsNamedPolygon('PGND') Or  IsNamedPolygon('BOTTOM_LAYER_NETC106_2_P030') Or  IsNamedPolygon('SIGNAL_LAYER_2_C102_1_P032') Or  IsNamedPolygon('C102_1') Or  IsNamedPolygon('SIGNAL_LAYER_4_C102_1_P038') Or  IsNamedPolygon('SGND') Or  IsNamedPolygon('SIGNAL_LAYER_1_IOUT_SNS_P044') Or  IsNamedPolygon('BOTTOM_LAYER_54V1_P128') Or  IsNamedPolygon('TOP_LAYER_54V2_P048') Or  IsNamedPolygon('BOTTOM_LAYER_54V1_P128') Or  IsNamedPolygon('TOP_LAYER_54V2_P048') Or  IsNamedPolygon('C108_1') Or  IsNamedPolygon('C108_1') Or  IsNamedPolygon('C108_1') Or  IsNamedPolygon('C108_1') Or  IsNamedPolygon('C108_1') Or  IsNamedPolygon('C108_1') Or  IsNamedPolygon('PGND') Or  IsNamedPolygon('ZCD') Or  IsNamedPolygon('Line') Or  IsNamedPolygon('5Vp') Or  IsNamedPolygon('12Vp') Or  IsNamedPolygon('T200_4') Or  IsNamedPolygon('T200_6') Or  IsNamedPolygon('SGND') Or  IsNamedPolygon('T200_4') Or  IsNamedPolygon('T200_6') Or  IsNamedPolygon('SGND') Or  IsNamedPolygon('VSR') Or  IsNamedPolygon('Iout_SNS') Or  IsNamedPolygon('SIGNAL_LAYER_2_VBB_P094') Or  IsNamedPolygon('BOTTOM_LAYER_VBULK1_P096') Or  IsNamedPolygon('Vbulk1') Or  IsNamedPolygon('VBB') Or  IsNamedPolygon('SIGNAL_LAYER_1_VBULK1_P106') Or  IsNamedPolygon('SIGNAL_LAYER_1_ZCD_P108') Or  IsNamedPolygon('Line') Or  IsNamedPolygon('Line') Or  IsNamedPolygon('Line') Or  IsNamedPolygon('D404_2') Or  IsNamedPolygon('VBB') Or  IsNamedPolygon('D400_2') Or  IsNamedPolygon('SGND') Or  IsNamedPolygon('PGND') Or  IsNamedPolygon('TOP_LAYER_12VS_P126') Or  IsNamedPolygon('BOTTOM_LAYER_54V1_P128') Or  IsNamedPolygon('LEG3_HS_DRV')] p34: connectstyle=Direct reliefconductorwidth=10 reliefentries=4 polygonreliefangle="90 Angle" airgapwidth=10
PolygonConnect PolygonConnect_34 [All vs IsNamedPolygon('SWNODE') Or  IsNamedPolygon('D403_2') Or  IsNamedPolygon('D403_2') Or  IsNamedPolygon('PGND') Or  IsNamedPolygon('BOTTOM_LAYER_NETC106_2_P030') Or  IsNamedPolygon('SIGNAL_LAYER_2_C102_1_P032') Or  IsNamedPolygon('C102_1') Or  IsNamedPolygon('SIGNAL_LAYER_4_C102_1_P038') Or  IsNamedPolygon('SGND') Or  IsNamedPolygon('SIGNAL_LAYER_1_IOUT_SNS_P044') Or  IsNamedPolygon('BOTTOM_LAYER_54V1_P128') Or  IsNamedPolygon('TOP_LAYER_54V2_P048') Or  IsNamedPolygon('BOTTOM_LAYER_54V1_P128') Or  IsNamedPolygon('TOP_LAYER_54V2_P048') Or  IsNamedPolygon('C108_1') Or  IsNamedPolygon('C108_1') Or  IsNamedPolygon('C108_1') Or  IsNamedPolygon('C108_1') Or  IsNamedPolygon('C108_1') Or  IsNamedPolygon('C108_1') Or  IsNamedPolygon('PGND') Or  IsNamedPolygon('ZCD') Or  IsNamedPolygon('Line') Or  IsNamedPolygon('5Vp') Or  IsNamedPolygon('12Vp') Or  IsNamedPolygon('T200_4') Or  IsNamedPolygon('T200_6') Or  IsNamedPolygon('SGND') Or  IsNamedPolygon('T200_4') Or  IsNamedPolygon('T200_6') Or  IsNamedPolygon('SGND') Or  IsNamedPolygon('VSR') Or  IsNamedPolygon('Iout_SNS') Or  IsNamedPolygon('SIGNAL_LAYER_2_VBB_P094') Or  IsNamedPolygon('BOTTOM_LAYER_VBULK1_P096') Or  IsNamedPolygon('Vbulk1') Or  IsNamedPolygon('VBB') Or  IsNamedPolygon('SIGNAL_LAYER_1_VBULK1_P106') Or  IsNamedPolygon('SIGNAL_LAYER_1_ZCD_P108') Or  IsNamedPolygon('Line') Or  IsNamedPolygon('Line') Or  IsNamedPolygon('Line') Or  IsNamedPolygon('D404_2') Or  IsNamedPolygon('VBB') Or  IsNamedPolygon('D400_2') Or  IsNamedPolygon('SGND')] p35: connectstyle=Direct reliefconductorwidth=10 reliefentries=4 polygonreliefangle="90 Angle" airgapwidth=10
PolygonConnect PolygonConnect_33 [All vs IsNamedPolygon('SIGNAL_LAYER_1_VBULK1_P106')] p36: connectstyle=Direct reliefconductorwidth=10 reliefentries=4 polygonreliefangle="90 Angle" airgapwidth=10
PolygonConnect PolygonConnect_32 [All vs IsNamedPolygon('SIGNAL_LAYER_1_VBULK1_P106')] p37: connectstyle=Direct reliefconductorwidth=10 reliefentries=4 polygonreliefangle="90 Angle" airgapwidth=10
PolygonConnect PolygonConnect_31 [All vs IsNamedPolygon('SIGNAL_LAYER_1_VBULK1_P106')] p38: connectstyle=Direct reliefconductorwidth=10 reliefentries=4 polygonreliefangle="90 Angle" airgapwidth=10
PolygonConnect PolygonConnect_30 [All vs IsNamedPolygon('VBB')] p39: connectstyle=Direct reliefconductorwidth=10 reliefentries=4 polygonreliefangle="90 Angle" airgapwidth=10
PolygonConnect PolygonConnect_29 [All vs IsNamedPolygon('SGND')] p40: connectstyle=Direct reliefconductorwidth=10 reliefentries=4 polygonreliefangle="90 Angle" airgapwidth=10
PolygonConnect PolygonConnect_28 [All vs IsNamedPolygon('Vbulk1')] p41: connectstyle=Direct reliefconductorwidth=10 reliefentries=4 polygonreliefangle="90 Angle" airgapwidth=10
PolygonConnect PolygonConnect_27 [All vs IsNamedPolygon('BOTTOM_LAYER_VBULK1_P096')] p42: connectstyle=Direct reliefconductorwidth=10 reliefentries=4 polygonreliefangle="90 Angle" airgapwidth=10
PolygonConnect PolygonConnect_26 [All vs IsNamedPolygon('SIGNAL_LAYER_2_VBB_P094')] p43: connectstyle=Direct reliefconductorwidth=10 reliefentries=4 polygonreliefangle="90 Angle" airgapwidth=10
PolygonConnect PolygonConnect_25 [All vs IsNamedPolygon('C108_1')] p44: connectstyle=Direct reliefconductorwidth=10 reliefentries=4 polygonreliefangle="90 Angle" airgapwidth=10
PolygonConnect PolygonConnect_24 [All vs IsNamedPolygon('BOTTOM_LAYER_EARTH_P100')] p45: connectstyle=Direct reliefconductorwidth=10 reliefentries=4 polygonreliefangle="90 Angle" airgapwidth=10
PolygonConnect PolygonConnect_23 [All vs IsNamedPolygon('BOTTOM_LAYER_54V1_P128')] p46: connectstyle=Direct reliefconductorwidth=10 reliefentries=4 polygonreliefangle="90 Angle" airgapwidth=10
PolygonConnect PolygonConnect_22 [All vs IsNamedPolygon('BOTTOM_LAYER_VBULK1_P096')] p47: connectstyle=Direct reliefconductorwidth=10 reliefentries=4 polygonreliefangle="90 Angle" airgapwidth=10
PolygonConnect PolygonConnect_21 [All vs IsNamedPolygon('SIGNAL_LAYER_2_VBB_P094')] p48: connectstyle=Direct reliefconductorwidth=10 reliefentries=4 polygonreliefangle="90 Angle" airgapwidth=10
PolygonConnect PolygonConnect_20 [All vs IsNamedPolygon('Iout_SNS')] p49: connectstyle=Direct reliefconductorwidth=10 reliefentries=4 polygonreliefangle="90 Angle" airgapwidth=10
PolygonConnect PolygonConnect_19 [All vs IsNamedPolygon('C108_1') Or  IsNamedPolygon('BOTTOM_LAYER_NETC106_2_P030') Or  IsNamedPolygon('D403_2') Or  IsNamedPolygon('C102_1') Or  IsNamedPolygon('SWNODE') Or  IsNamedPolygon('D403_2') Or  IsNamedPolygon('SIGNAL_LAYER_4_C102_1_P038') Or  IsNamedPolygon('PGND') Or  IsNamedPolygon('SIGNAL_LAYER_2_C102_1_P032') Or  IsNamedPolygon('SIGNAL_LAYER_1_IOUT_SNS_P044') Or  IsNamedPolygon('SGND') Or  IsNamedPolygon('C108_1') Or  IsNamedPolygon('BOTTOM_LAYER_54V1_P128') Or  IsNamedPolygon('C108_1') Or  IsNamedPolygon('C108_1') Or  IsNamedPolygon('TOP_LAYER_54V2_P048') Or  IsNamedPolygon('BOTTOM_LAYER_54V1_P128') Or  IsNamedPolygon('TOP_LAYER_54V2_P048') Or  IsNamedPolygon('C108_1') Or  IsNamedPolygon('C108_1') Or  IsNamedPolygon('12Vp') Or  IsNamedPolygon('5Vp') Or  IsNamedPolygon('Line') Or  IsNamedPolygon('T200_4') Or  IsNamedPolygon('SGND') Or  IsNamedPolygon('VSR') Or  IsNamedPolygon('ZCD') Or  IsNamedPolygon('PGND') Or  IsNamedPolygon('T200_6') Or  IsNamedPolygon('Neutral') Or  IsNamedPolygon('T200_4') Or  IsNamedPolygon('SGND') Or  IsNamedPolygon('T200_6')] p50: connectstyle=Direct reliefconductorwidth=10 reliefentries=4 polygonreliefangle="90 Angle" airgapwidth=10
PolygonConnect PolygonConnect_18 [All vs IsNamedPolygon('SWNODE') Or  IsNamedPolygon('D403_2') Or  IsNamedPolygon('D403_2') Or  IsNamedPolygon('PGND') Or  IsNamedPolygon('BOTTOM_LAYER_NETC106_2_P030') Or  IsNamedPolygon('SIGNAL_LAYER_2_C102_1_P032') Or  IsNamedPolygon('C102_1') Or  IsNamedPolygon('SIGNAL_LAYER_4_C102_1_P038') Or  IsNamedPolygon('SGND') Or  IsNamedPolygon('SIGNAL_LAYER_1_IOUT_SNS_P044') Or  IsNamedPolygon('BOTTOM_LAYER_54V1_P128') Or  IsNamedPolygon('TOP_LAYER_54V2_P048') Or  IsNamedPolygon('BOTTOM_LAYER_54V1_P128') Or  IsNamedPolygon('TOP_LAYER_54V2_P048') Or  IsNamedPolygon('C108_1') Or  IsNamedPolygon('C108_1') Or  IsNamedPolygon('C108_1') Or  IsNamedPolygon('C108_1') Or  IsNamedPolygon('C108_1') Or  IsNamedPolygon('C108_1') Or  IsNamedPolygon('Neutral') Or  IsNamedPolygon('PGND') Or  IsNamedPolygon('ZCD') Or  IsNamedPolygon('Line') Or  IsNamedPolygon('5Vp') Or  IsNamedPolygon('12Vp') Or  IsNamedPolygon('T200_4') Or  IsNamedPolygon('T200_6') Or  IsNamedPolygon('SGND') Or  IsNamedPolygon('T200_4') Or  IsNamedPolygon('T200_6') Or  IsNamedPolygon('SGND')] p51: connectstyle=Direct reliefconductorwidth=10 reliefentries=4 polygonreliefangle="90 Angle" airgapwidth=10
PolygonConnect PolygonConnect_17 [All vs IsNamedPolygon('12Vp') Or  IsNamedPolygon('T200_4') Or  IsNamedPolygon('T200_6') Or  IsNamedPolygon('SGND') Or  IsNamedPolygon('TOP_LAYER_54V2_P048') Or  IsNamedPolygon('SIGNAL_LAYER_1_IOUT_SNS_P044') Or  IsNamedPolygon('BOTTOM_LAYER_54V1_P128') Or  IsNamedPolygon('SGND') Or  IsNamedPolygon('C102_1') Or  IsNamedPolygon('SIGNAL_LAYER_4_C102_1_P038') Or  IsNamedPolygon('Neutral') Or  IsNamedPolygon('C108_1') Or  IsNamedPolygon('C108_1') Or  IsNamedPolygon('C108_1') Or  IsNamedPolygon('BOTTOM_LAYER_54V1_P128') Or  IsNamedPolygon('TOP_LAYER_54V2_P048') Or  IsNamedPolygon('SIGNAL_LAYER_2_C102_1_P032') Or  IsNamedPolygon('SWNODE') Or  IsNamedPolygon('C108_1') Or  IsNamedPolygon('C108_1') Or  IsNamedPolygon('C108_1') Or  IsNamedPolygon('D403_2') Or  IsNamedPolygon('BOTTOM_LAYER_NETC106_2_P030') Or  IsNamedPolygon('PGND') Or  IsNamedPolygon('D403_2') Or  IsNamedPolygon('5Vp') Or  IsNamedPolygon('PGND') Or  IsNamedPolygon('ZCD') Or  IsNamedPolygon('Line')] p52: connectstyle=Direct reliefconductorwidth=10 reliefentries=4 polygonreliefangle="90 Angle" airgapwidth=10
PolygonConnect PolygonConnect_16 [All vs IsNamedPolygon('D403_2') Or  IsNamedPolygon('C102_1') Or  IsNamedPolygon('C108_1') Or  IsNamedPolygon('SWNODE') Or  IsNamedPolygon('BOTTOM_LAYER_54V1_P128') Or  IsNamedPolygon('SGND') Or  IsNamedPolygon('Line') Or  IsNamedPolygon('ZCD') Or  IsNamedPolygon('SIGNAL_LAYER_1_IOUT_SNS_P044') Or  IsNamedPolygon('Neutral') Or  IsNamedPolygon('PGND') Or  IsNamedPolygon('12Vp') Or  IsNamedPolygon('C108_1') Or  IsNamedPolygon('C108_1') Or  IsNamedPolygon('TOP_LAYER_54V2_P048') Or  IsNamedPolygon('C108_1') Or  IsNamedPolygon('TOP_LAYER_54V2_P048') Or  IsNamedPolygon('T200_4') Or  IsNamedPolygon('T200_6') Or  IsNamedPolygon('D403_2') Or  IsNamedPolygon('C108_1') Or  IsNamedPolygon('C108_1') Or  IsNamedPolygon('SIGNAL_LAYER_4_C102_1_P038') Or  IsNamedPolygon('SIGNAL_LAYER_2_C102_1_P032') Or  IsNamedPolygon('PGND') Or  IsNamedPolygon('BOTTOM_LAYER_NETC106_2_P030') Or  IsNamedPolygon('5Vp') Or  IsNamedPolygon('BOTTOM_LAYER_54V1_P128')] p53: connectstyle=Direct reliefconductorwidth=10 reliefentries=4 polygonreliefangle="90 Angle" airgapwidth=10
PolygonConnect PolygonConnect_15 [All vs IsNamedPolygon('SWNODE') Or  IsNamedPolygon('D403_2') Or  IsNamedPolygon('D403_2') Or  IsNamedPolygon('SIGNAL_LAYER_1_PGND_P018') Or  IsNamedPolygon('PGND') Or  IsNamedPolygon('BOTTOM_LAYER_NETC106_2_P030') Or  IsNamedPolygon('SIGNAL_LAYER_2_C102_1_P032') Or  IsNamedPolygon('C102_1') Or  IsNamedPolygon('SIGNAL_LAYER_4_C102_1_P038') Or  IsNamedPolygon('SGND') Or  IsNamedPolygon('SIGNAL_LAYER_1_IOUT_SNS_P044') Or  IsNamedPolygon('BOTTOM_LAYER_54V1_P128') Or  IsNamedPolygon('TOP_LAYER_54V2_P048') Or  IsNamedPolygon('BOTTOM_LAYER_54V1_P128') Or  IsNamedPolygon('TOP_LAYER_54V2_P048') Or  IsNamedPolygon('C108_1') Or  IsNamedPolygon('C108_1') Or  IsNamedPolygon('C108_1') Or  IsNamedPolygon('C108_1') Or  IsNamedPolygon('C108_1') Or  IsNamedPolygon('C108_1') Or  IsNamedPolygon('Neutral') Or  IsNamedPolygon('PGND') Or  IsNamedPolygon('ZCD') Or  IsNamedPolygon('Line') Or  IsNamedPolygon('5Vp') Or  IsNamedPolygon('12Vp')] p54: connectstyle=Direct reliefconductorwidth=10 reliefentries=4 polygonreliefangle="90 Angle" airgapwidth=10
PolygonConnect PolygonConnect_14 [All vs IsNamedPolygon('TOP_LAYER_54V2_P048') Or  IsNamedPolygon('C108_1') Or  IsNamedPolygon('C108_1') Or  IsNamedPolygon('SIGNAL_LAYER_4_C102_1_P038') Or  IsNamedPolygon('C102_1') Or  IsNamedPolygon('SIGNAL_LAYER_2_C102_1_P032') Or  IsNamedPolygon('SIGNAL_LAYER_1_PGND_P018') Or  IsNamedPolygon('SIGNAL_LAYER_1_IOUT_SNS_P044') Or  IsNamedPolygon('SGND') Or  IsNamedPolygon('C108_1') Or  IsNamedPolygon('ZCD') Or  IsNamedPolygon('PGND') Or  IsNamedPolygon('TOP_LAYER_54V2_P048') Or  IsNamedPolygon('BOTTOM_LAYER_NETC106_2_P030') Or  IsNamedPolygon('PGND') Or  IsNamedPolygon('C108_1') Or  IsNamedPolygon('C108_1') Or  IsNamedPolygon('D403_2') Or  IsNamedPolygon('Line') Or  IsNamedPolygon('C108_1') Or  IsNamedPolygon('Neutral') Or  IsNamedPolygon('SWNODE') Or  IsNamedPolygon('D403_2') Or  IsNamedPolygon('BOTTOM_LAYER_54V1_P128') Or  IsNamedPolygon('BOTTOM_LAYER_54V1_P128')] p55: connectstyle=Direct reliefconductorwidth=10 reliefentries=4 polygonreliefangle="90 Angle" airgapwidth=10
PolygonConnect PolygonConnect_13 [All vs IsNamedPolygon('PGND') Or  IsNamedPolygon('D403_2') Or  IsNamedPolygon('SIGNAL_LAYER_1_PGND_P018') Or  IsNamedPolygon('D403_2') Or  IsNamedPolygon('SWNODE') Or  IsNamedPolygon('SGND') Or  IsNamedPolygon('BOTTOM_LAYER_54V1_P128') Or  IsNamedPolygon('C108_1') Or  IsNamedPolygon('SIGNAL_LAYER_4_C102_1_P038') Or  IsNamedPolygon('C108_1') Or  IsNamedPolygon('TOP_LAYER_54V2_P048') Or  IsNamedPolygon('TOP_LAYER_54V2_P048') Or  IsNamedPolygon('C108_1') Or  IsNamedPolygon('C108_1') Or  IsNamedPolygon('C108_1') Or  IsNamedPolygon('BOTTOM_LAYER_NETC106_2_P030') Or  IsNamedPolygon('SIGNAL_LAYER_1_IOUT_SNS_P044') Or  IsNamedPolygon('C108_1') Or  IsNamedPolygon('C102_1') Or  IsNamedPolygon('SIGNAL_LAYER_2_C102_1_P032') Or  IsNamedPolygon('BOTTOM_LAYER_54V1_P128')] p56: connectstyle=Direct reliefconductorwidth=10 reliefentries=4 polygonreliefangle="90 Angle" airgapwidth=10
PolygonConnect PolygonConnect_12 [All vs IsNamedPolygon('TOP_LAYER_54V2_P048')] p57: connectstyle=Direct reliefconductorwidth=10 reliefentries=4 polygonreliefangle="90 Angle" airgapwidth=10
PolygonConnect PolygonConnect_11 [All vs IsNamedPolygon('BOTTOM_LAYER_54V1_P128')] p58: connectstyle=Direct reliefconductorwidth=10 reliefentries=4 polygonreliefangle="90 Angle" airgapwidth=10
PolygonConnect PolygonConnect_10 [All vs IsNamedPolygon('SIGNAL_LAYER_1_IOUT_SNS_P044')] p59: thpad.connectstyle=Direct thpad.reliefconductorwidth=10 thpad.reliefentries=4 thpad.polygonreliefangle="90 Angle" thpad.airgapwidth=10 smdpad.connectstyle=Relief smdpad.reliefconductorwidth=10 smdpad.reliefentries=4 smdpad.polygonreliefangle="90 Angle" smdpad.airgapwidth=10 via.connectstyle=Direct via.reliefconductorwidth=10 via.reliefentries=4 via.polygonreliefangle="90 Angle" via.airgapwidth=10
PolygonConnect PolygonConnect_9 [All vs IsNamedPolygon('SGND')] p60: thpad.connectstyle=Direct thpad.reliefconductorwidth=10 thpad.reliefentries=4 thpad.polygonreliefangle="90 Angle" thpad.airgapwidth=10 smdpad.connectstyle=Relief smdpad.reliefconductorwidth=10 smdpad.reliefentries=4 smdpad.polygonreliefangle="90 Angle" smdpad.airgapwidth=10 via.connectstyle=Direct via.reliefconductorwidth=10 via.reliefentries=4 via.polygonreliefangle="90 Angle" via.airgapwidth=10
PolygonConnect PolygonConnect_8 [All vs IsNamedPolygon('SGND')] p61: thpad.connectstyle=Direct thpad.reliefconductorwidth=10 thpad.reliefentries=4 thpad.polygonreliefangle="90 Angle" thpad.airgapwidth=10 smdpad.connectstyle=Relief smdpad.reliefconductorwidth=10 smdpad.reliefentries=4 smdpad.polygonreliefangle="90 Angle" smdpad.airgapwidth=10 via.connectstyle=Direct via.reliefconductorwidth=10 via.reliefentries=4 via.polygonreliefangle="90 Angle" via.airgapwidth=10
PolygonConnect PolygonConnect_7 [All vs IsNamedPolygon('SGND')] p62: thpad.connectstyle=Relief thpad.reliefconductorwidth=0 thpad.reliefentries=4 thpad.polygonreliefangle="90 Angle" thpad.airgapwidth=0 smdpad.connectstyle=Relief smdpad.reliefconductorwidth=10 smdpad.reliefentries=4 smdpad.polygonreliefangle="90 Angle" smdpad.airgapwidth=10 via.connectstyle=Relief via.reliefconductorwidth=10 via.reliefentries=4 via.polygonreliefangle="90 Angle" via.airgapwidth=10
PolygonConnect PolygonConnect_6 [All vs IsNamedPolygon('SGND')] p63: thpad.connectstyle=Direct thpad.reliefconductorwidth=10 thpad.reliefentries=4 thpad.polygonreliefangle="90 Angle" thpad.airgapwidth=10 smdpad.connectstyle=Relief smdpad.reliefconductorwidth=10 smdpad.reliefentries=4 smdpad.polygonreliefangle="90 Angle" smdpad.airgapwidth=10 via.connectstyle=Relief via.reliefconductorwidth=10 via.reliefentries=4 via.polygonreliefangle="90 Angle" via.airgapwidth=10
PolygonConnect PolygonConnect_5 [All vs IsNamedPolygon('SGND')] p64: thpad.connectstyle=Direct thpad.reliefconductorwidth=10 thpad.reliefentries=4 thpad.polygonreliefangle="90 Angle" thpad.airgapwidth=10 smdpad.connectstyle=Relief smdpad.reliefconductorwidth=10 smdpad.reliefentries=4 smdpad.polygonreliefangle="90 Angle" smdpad.airgapwidth=10 via.connectstyle=Relief via.reliefconductorwidth=10 via.reliefentries=4 via.polygonreliefangle="90 Angle" via.airgapwidth=10
PolygonConnect PolygonConnect_4 [All vs IsNamedPolygon('SIGNAL_LAYER_1_PGND_P018') Or  IsNamedPolygon('SWNODE') Or  IsNamedPolygon('D403_2') Or  IsNamedPolygon('SIGNAL_LAYER_4_C102_1_P038') Or  IsNamedPolygon('D403_2') Or  IsNamedPolygon('BOTTOM_LAYER_NETC106_2_P030') Or  IsNamedPolygon('C102_1') Or  IsNamedPolygon('PGND') Or  IsNamedPolygon('SIGNAL_LAYER_2_C102_1_P032')] p65: connectstyle=Direct reliefconductorwidth=10 reliefentries=4 polygonreliefangle="90 Angle" airgapwidth=10
PolygonConnect PolygonConnect_3 [All vs IsNamedPolygon('SWNODE') Or  IsNamedPolygon('D403_2') Or  IsNamedPolygon('Neutral') Or  IsNamedPolygon('C106_2') Or  IsNamedPolygon('D403_2') Or  IsNamedPolygon('Neutral') Or  IsNamedPolygon('Neutral')] p66: connectstyle=Direct reliefconductorwidth=10 reliefentries=4 polygonreliefangle="90 Angle" airgapwidth=10
PolygonConnect PolygonConnect_2 [All vs IsNamedPolygon('Neutral') Or  IsNamedPolygon('Neutral') Or  IsNamedPolygon('C106_2') Or  IsNamedPolygon('SWNODE') Or  IsNamedPolygon('Neutral')] p67: connectstyle=Direct reliefconductorwidth=10 reliefentries=4 polygonreliefangle="90 Angle" airgapwidth=10
PolygonConnect PolygonConnect_1 [All vs IsNamedPolygon('Neutral') Or  IsNamedPolygon('Neutral')] p68: connectstyle=Direct reliefconductorwidth=10 reliefentries=4 polygonreliefangle="90 Angle" airgapwidth=10
PolygonConnect [All] p69: connectstyle=Relief reliefconductorwidth=10 reliefentries=4 polygonreliefangle="90 Angle" airgapwidth=10
RoutingVias ThermalPadVias [IsVia and InAnyComponent] p1: holewidth=7.87 width=19.68 viastyle="Through Hole" minholewidth=7.87 minwidth=19.68 maxholewidth=12.99 maxwidth=23.62
RoutingVias [All] p2: holewidth=16 width=34 viastyle="Through Hole" minholewidth=7.87 minwidth=20 maxholewidth=40 maxwidth=65
SilkToBoardRegionClearance [Not ((IsComment or IsDesignator) And (Hide <> 'False')) and not InRegion(1000,500,4000,800)] p1:
